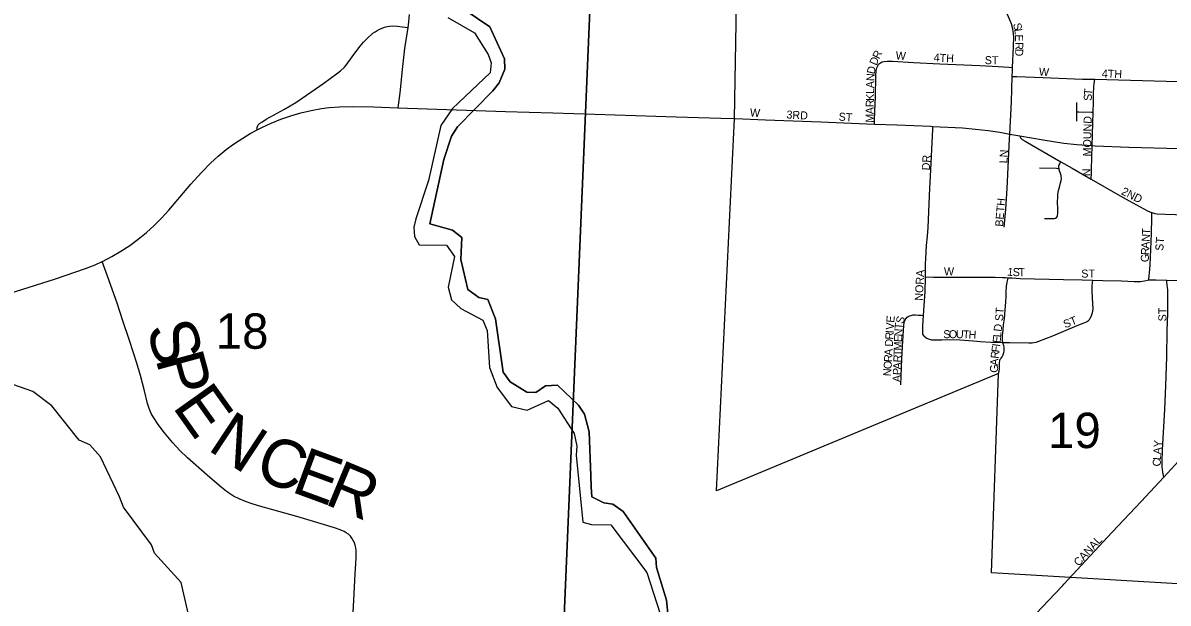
# Model space of a CAD drawing. Extents: x 0 to 34, y 0 to 22.
# Drawn here: x 3.441 to 4.796, y 17.694 to 18.381 of the extents above; entities that cross this region are included whole.
import ezdxf

# ---------------------------------------------------------------- set-up
doc = ezdxf.new("R2010")
doc.units = 0
for name, color, linetype in [('GM_X_City_Street', 7, 'Continuous'), ('GM_X_City_Street_Text', 7, 'Continuous'), ('GM_X_Corporation', 7, 'Continuous'), ('GM_X_County_Road', 7, 'Continuous'), ('GM_X_Minor_River', 7, 'Continuous'), ('GM_X_Section', 7, 'Continuous'), ('GM_X_Section_Text', 7, 'Continuous'), ('GM_X_Township_Road', 7, 'Continuous'), ('GM_X_Township_Road_Text', 7, 'Continuous')]:
    doc.layers.add(name, color=color, linetype=linetype)

msp = doc.modelspace()

# ---------------------------------------------------------------- linework, layer by layer
at = {"layer": 'GM_X_City_Street'}
for points in [[(4.6123, 18.3277), (4.6134, 18.3522), (4.6135, 18.3645), (4.6129, 18.3706), (4.6124, 18.3736), (4.6108, 18.3794), (4.6075, 18.388), (4.5998, 18.4049), (4.5947, 18.4162), (4.5925, 18.422), (4.5907, 18.4281), (4.5897, 18.4343), (4.5893, 18.4405), (4.5894, 18.453), (4.5903, 18.4799), (4.5904, 18.4842)], [(4.4486, 18.261), (4.4488, 18.2646), (4.4493, 18.2765), (4.45, 18.293), (4.4504, 18.3183), (4.4508, 18.3242), (4.4515, 18.3274), (4.4526, 18.3299), (4.4537, 18.3317)], [(4.4537, 18.3317), (4.4547, 18.3327), (4.4559, 18.3335), (4.458, 18.3344), (4.4602, 18.3351), (4.4638, 18.3355), (4.4701, 18.3354), (4.4951, 18.3338), (4.5263, 18.3321), (4.5733, 18.3302), (4.5951, 18.3291), (4.6076, 18.3281), (4.6123, 18.3277)], [(4.6119, 18.3173), (4.6121, 18.3244), (4.6123, 18.3277)], [(4.6089, 18.2491), (4.6109, 18.2872), (4.6119, 18.3173)], [(4.6119, 18.3173), (4.6172, 18.3171), (4.6482, 18.316), (4.6948, 18.3142), (4.7094, 18.3139)], [(4.7076, 18.2752), (4.7078, 18.2868), (4.708, 18.2961), (4.7085, 18.3054), (4.7088, 18.3084), (4.7094, 18.3139)], [(4.7094, 18.3139), (4.7939, 18.3118), (4.8368, 18.3107), (4.8711, 18.3097)], [(4.6883, 18.2754), (4.6884, 18.2865)], [(4.6882, 18.2645), (4.6883, 18.2754)], [(4.6883, 18.2754), (4.6908, 18.2754), (4.7054, 18.2752), (4.7076, 18.2752)], [(4.7065, 18.2354), (4.7073, 18.2619), (4.7076, 18.2752)], [(4.2837, 18.2675), (4.2838, 18.2675), (4.3199, 18.266), (4.3852, 18.2635), (4.4486, 18.261)], [(4.4486, 18.261), (4.4752, 18.2599), (4.5156, 18.2583), (4.5178, 18.2582)], [(4.5091, 18.0802), (4.5091, 18.0955), (4.5094, 18.1018), (4.5104, 18.1174), (4.5114, 18.1284), (4.5122, 18.1387), (4.5139, 18.1759), (4.5143, 18.1851), (4.5151, 18.199), (4.5177, 18.2551), (4.5178, 18.2582)], [(4.5178, 18.2582), (4.5528, 18.2564), (4.5684, 18.2551), (4.5835, 18.2535), (4.5973, 18.2512), (4.6089, 18.2491)], [(4.6022, 18.1388), (4.6041, 18.1602), (4.6056, 18.1848), (4.6086, 18.2433), (4.6089, 18.2491)], [(4.6089, 18.2491), (4.6207, 18.247)], [(4.6207, 18.247), (4.6217, 18.2447), (4.6236, 18.2428), (4.6269, 18.2407), (4.6694, 18.2163)], [(4.6207, 18.247), (4.6482, 18.2422), (4.6727, 18.2385), (4.6882, 18.2368), (4.7065, 18.2354)], [(4.7053, 18.1957), (4.7056, 18.2032), (4.7057, 18.2072), (4.7065, 18.2354)], [(4.7065, 18.2354), (4.7098, 18.2351), (4.7498, 18.2337), (4.8247, 18.2318), (4.8651, 18.2306), (4.8682, 18.2305)], [(4.6672, 18.2084), (4.667, 18.2099), (4.6671, 18.2114), (4.6675, 18.2127), (4.6682, 18.214), (4.6694, 18.2163)], [(4.6694, 18.2163), (4.6828, 18.2086), (4.7053, 18.1957)], [(4.6441, 18.2092), (4.6641, 18.2086), (4.6672, 18.2084)], [(4.6501, 18.1493), (4.6586, 18.1491), (4.6615, 18.1491), (4.6631, 18.1496), (4.6644, 18.1508), (4.6653, 18.1527), (4.6657, 18.1553), (4.6656, 18.16), (4.6655, 18.1694), (4.6656, 18.1742), (4.6659, 18.1779), (4.6666, 18.1824), (4.6682, 18.1878), (4.6691, 18.1913), (4.6697, 18.194), (4.6699, 18.1963), (4.6696, 18.2), (4.6691, 18.2026), (4.6675, 18.2069), (4.6672, 18.2084)], [(4.7053, 18.1957), (4.7366, 18.1778), (4.7501, 18.1701), (4.7719, 18.1584), (4.7747, 18.1572), (4.7769, 18.1564)], [(4.7736, 18.0765), (4.7739, 18.0818), (4.7741, 18.0849), (4.7749, 18.0942), (4.7755, 18.1034), (4.7759, 18.1127), (4.7766, 18.1313), (4.7768, 18.15), (4.7769, 18.1564)], [(4.7769, 18.1564), (4.7804, 18.1553), (4.7834, 18.1548), (4.7926, 18.1542), (4.8652, 18.152)], [(4.5069, 18.0346), (4.5077, 18.0462), (4.5086, 18.0626), (4.5091, 18.0802)], [(4.5091, 18.0802), (4.5186, 18.08), (4.5306, 18.0798), (4.5585, 18.0797), (4.5914, 18.0798), (4.6004, 18.0796), (4.604, 18.0794), (4.607, 18.0792)], [(4.6008, 18.0026), (4.6004, 18.0044), (4.6001, 18.0066), (4.6001, 18.01), (4.6005, 18.014), (4.601, 18.0176), (4.6016, 18.0235), (4.6025, 18.0305), (4.6036, 18.041), (4.6043, 18.0502), (4.6045, 18.0574), (4.6045, 18.0624), (4.6051, 18.0687), (4.6057, 18.074), (4.6065, 18.0771), (4.607, 18.0792)], [(4.607, 18.0792), (4.6114, 18.0789), (4.6213, 18.0784), (4.6726, 18.0772), (4.6944, 18.0768), (4.707, 18.0763)], [(4.7042, 18.0313), (4.7055, 18.0339), (4.7064, 18.0367), (4.7071, 18.0397), (4.7074, 18.0422), (4.7073, 18.0482), (4.7063, 18.0634), (4.7063, 18.0667), (4.7065, 18.0692), (4.7068, 18.074), (4.707, 18.0763)], [(4.707, 18.0763), (4.7189, 18.0759), (4.7409, 18.0753), (4.7562, 18.0748), (4.7635, 18.0748), (4.7683, 18.0754), (4.772, 18.0764), (4.7736, 18.0765)], [(4.7736, 18.0765), (4.7768, 18.0767), (4.7819, 18.0767), (4.7946, 18.0763)], [(4.791, 17.843), (4.7902, 17.8491), (4.7894, 17.8553), (4.7892, 17.8615), (4.7898, 17.8754), (4.7923, 17.9234), (4.7935, 17.9513), (4.7947, 17.9854), (4.7952, 18.0164), (4.7959, 18.0371), (4.796, 18.0552), (4.7959, 18.0649), (4.7949, 18.0734), (4.7946, 18.0763)], [(4.7946, 18.0763), (4.8624, 18.0744)], [(4.48, 17.9524), (4.4813, 17.983), (4.4823, 18.0043), (4.4834, 18.0227), (4.4838, 18.0257), (4.4842, 18.0274), (4.485, 18.0293), (4.4858, 18.0305), (4.4874, 18.0323), (4.4887, 18.0332), (4.4902, 18.0339), (4.4921, 18.0346), (4.4944, 18.0351), (4.4975, 18.0352), (4.5006, 18.035), (4.504, 18.0348), (4.5069, 18.0346)], [(4.5076, 18.0099), (4.5067, 18.0111), (4.5061, 18.0123), (4.5058, 18.0141), (4.5059, 18.0181), (4.506, 18.0222), (4.5069, 18.0346)], [(4.6008, 18.0026), (4.6084, 18.0025), (4.6314, 18.0022), (4.6353, 18.0023), (4.6375, 18.0025), (4.6402, 18.0031), (4.6431, 18.0039), (4.6597, 18.0105), (4.6887, 18.0225), (4.6958, 18.0254), (4.6995, 18.027), (4.701, 18.0278), (4.7022, 18.0286), (4.7032, 18.0297), (4.7042, 18.0313)], [(4.5076, 18.0099), (4.5094, 18.0084), (4.5106, 18.0077), (4.5122, 18.007), (4.5139, 18.0064), (4.5163, 18.0058), (4.5182, 18.0058), (4.5214, 18.0057), (4.5284, 18.0058), (4.5373, 18.006), (4.5499, 18.0056), (4.5661, 18.0044), (4.5738, 18.0038), (4.5868, 18.0029), (4.6008, 18.0026)], [(4.5956, 17.9659), (4.5965, 17.9687), (4.5967, 17.9717), (4.5966, 17.9755), (4.5967, 17.9783), (4.5971, 17.9809), (4.5977, 17.9826), (4.5986, 17.984), (4.5997, 17.9855), (4.6009, 17.9878), (4.6018, 17.9906), (4.6022, 17.9924), (4.6023, 17.9952), (4.6022, 17.9972), (4.6018, 17.999), (4.6012, 18.0007), (4.6008, 18.0026)], [(4.791, 17.843), (4.8172, 17.8715), (4.8363, 17.892), (4.8447, 17.9013), (4.8506, 17.9084), (4.8544, 17.9137), (4.8566, 17.9182)], [(4.6715, 17.7152), (4.6729, 17.7167), (4.7301, 17.778), (4.7644, 17.8142), (4.791, 17.843)]]:
    msp.add_lwpolyline(points, dxfattribs=at)
at = {"layer": 'GM_X_Corporation'}
msp.add_lwpolyline([(4.9748, 17.7073), (4.5871, 17.7299), (4.5956, 17.9659), (4.2619, 17.827), (4.283, 18.2672), (4.2872, 18.4939), (4.5904, 18.485), (4.6993, 18.4813), (4.7077, 18.686), (4.5833, 18.6907), (4.4929, 18.7467), (4.5036, 18.7609), (4.4834, 18.7705), (4.4977, 18.7812), (4.5483, 18.7776), (4.7237, 18.8109), (5.1009, 18.7931)], dxfattribs=at)
at = {"layer": 'GM_X_County_Road'}
for points in [[(3.8982, 18.3905), (3.8969, 18.3781), (3.8964, 18.3752)], [(3.8964, 18.3752), (3.8927, 18.3505), (3.8902, 18.3289), (3.887, 18.298), (3.8847, 18.2802)], [(3.7184, 18.2541), (3.7237, 18.2569), (3.7349, 18.2622), (3.7464, 18.2668), (3.7581, 18.2708), (3.77, 18.2742), (3.7821, 18.277), (3.7942, 18.2792), (3.8034, 18.2804), (3.8158, 18.2813), (3.8313, 18.2817), (3.8561, 18.2813), (3.8847, 18.2802)], [(3.8847, 18.2802), (4.0123, 18.276), (4.0682, 18.2742), (4.1179, 18.2727), (4.2142, 18.2696), (4.2669, 18.2679), (4.2837, 18.2675)], [(3.5349, 18.0983), (3.5351, 18.0984), (3.5462, 18.1042), (3.557, 18.1105), (3.5674, 18.1174), (3.5774, 18.1247), (3.5871, 18.1326), (3.5964, 18.141), (3.6052, 18.1498), (3.6137, 18.1589), (3.6398, 18.1897), (3.6522, 18.2036), (3.663, 18.2147), (3.6721, 18.2231), (3.6816, 18.231), (3.6891, 18.2365), (3.6968, 18.2416), (3.7101, 18.2496), (3.7184, 18.2541)], [(3.1436, 17.9953), (3.1996, 17.9978), (3.2183, 17.999), (3.2306, 18.0004), (3.243, 18.0023), (3.2522, 18.0041), (3.2612, 18.0065), (3.273, 18.0102), (3.2908, 18.0158), (3.3439, 18.0333), (3.3763, 18.044), (3.4324, 18.0627), (3.4797, 18.0779), (3.5149, 18.0901), (3.5266, 18.0945), (3.5349, 18.0983)], [(4.2855, 17.341), (4.2918, 17.3468), (4.325, 17.3794), (4.3475, 17.4009), (4.4085, 17.4585), (4.4377, 17.4863), (4.4812, 17.528), (4.5413, 17.5847), (4.5865, 17.6273), (4.6065, 17.6468), (4.626, 17.6668), (4.6622, 17.7052), (4.6715, 17.7152)]]:
    msp.add_lwpolyline(points, dxfattribs=at)
at = {"layer": 'GM_X_Minor_River'}
for points in [[(4.2049, 17.6739), (4.2025, 17.6978), (4.1907, 17.7365), (4.1899, 17.7475), (4.1514, 17.8024), (4.1393, 17.8111), (4.1283, 17.8129), (4.1142, 17.8201), (4.1134, 17.8318), (4.113, 17.8447), (4.1113, 17.8967), (4.1056, 17.9179), (4.0987, 17.9285), (4.0736, 17.952), (4.0596, 17.9512), (4.0479, 17.9435), (4.0373, 17.9439), (4.0175, 17.956), (4.0092, 17.9673), (4.0002, 18.0306), (3.9911, 18.0534), (3.9804, 18.0556), (3.9675, 18.0654), (3.9591, 18.1007), (3.9605, 18.1269), (3.9495, 18.1355), (3.9226, 18.143), (3.939, 18.219), (3.9484, 18.2467), (3.9552, 18.2577), (3.9971, 18.3003), (4.0046, 18.3098), (4.0114, 18.3258), (4.011, 18.3383), (3.9934, 18.3758), (3.9216, 18.4249)], [(3.9216, 18.4249), (3.9934, 18.3758), (4.011, 18.3383), (4.0114, 18.3258), (4.0046, 18.3098), (3.9971, 18.3003), (3.9552, 18.2577), (3.9484, 18.2467), (3.939, 18.219), (3.9226, 18.143), (3.9495, 18.1355), (3.9605, 18.1269), (3.9591, 18.1007), (3.9675, 18.0654), (3.9804, 18.0556), (3.9911, 18.0534), (4.0002, 18.0306), (4.0092, 17.9673), (4.0175, 17.956), (4.0373, 17.9439), (4.0479, 17.9435), (4.0596, 17.9512), (4.0736, 17.952), (4.0987, 17.9285), (4.1056, 17.9179), (4.1113, 17.8967), (4.113, 17.8447), (4.1134, 17.8318), (4.1142, 17.8201), (4.1283, 17.8129), (4.1393, 17.8111), (4.1514, 17.8024), (4.1899, 17.7475), (4.1907, 17.7365), (4.2025, 17.6978), (4.2049, 17.6739)], [(3.9437, 18.387), (3.9756, 18.3689), (3.9916, 18.3432), (3.9951, 18.3333), (3.994, 18.3215), (3.9494, 18.2793), (3.9354, 18.2592), (3.9209, 18.1943), (3.9059, 18.1487), (3.9036, 18.1388), (3.9044, 18.1278), (3.9101, 18.118), (3.9423, 18.1177), (3.9519, 18.1041), (3.9444, 18.068), (3.9482, 18.0529), (3.9593, 18.0426), (3.9851, 18.0291), (3.9904, 18.0169), (3.9932, 17.973), (4.0024, 17.9491), (4.0191, 17.9268), (4.0377, 17.9226), (4.0631, 17.9337), (4.0741, 17.9247), (4.0935, 17.8947), (4.0966, 17.88), (4.0959, 17.8693), (4.1037, 17.7901), (4.1139, 17.7871), (4.1367, 17.7868), (4.1793, 17.7304), (4.1992, 17.6694)], [(3.6381, 17.6644), (3.6391, 17.6722), (3.6284, 17.7184), (3.5968, 17.7532), (3.593, 17.7631), (3.5602, 17.8078), (3.5553, 17.8199), (3.5328, 17.8672), (3.5202, 17.8816), (3.5077, 17.8869), (3.4753, 17.9277), (3.4526, 17.9447), (3.3812, 17.9695)]]:
    msp.add_lwpolyline(points, dxfattribs=at)
at = {"layer": 'GM_X_Section'}
for points in [[(4.1166, 18.5074), (4.0746, 17.5111), (3.0654, 17.5504), (3.0927, 18.5447)], [(4.1166, 18.5074), (5.1195, 18.4619), (5.0805, 17.4591), (4.0746, 17.5111)]]:
    msp.add_lwpolyline(points, close=True, dxfattribs=at)
at = {"layer": 'GM_X_Township_Road'}
for points in [[(3.7184, 18.2541), (3.7184, 18.2567), (3.7188, 18.2582), (3.7196, 18.2602), (3.7211, 18.2615), (3.7236, 18.2633), (3.7288, 18.2667), (3.7505, 18.2786), (3.7638, 18.2866), (3.7767, 18.2951), (3.797, 18.3094), (3.8121, 18.3202), (3.817, 18.324), (3.8215, 18.3283), (3.8235, 18.3306), (3.8325, 18.3432), (3.84, 18.353), (3.844, 18.3578), (3.8483, 18.3622), (3.8553, 18.3684), (3.8578, 18.3702), (3.8604, 18.3718), (3.8631, 18.3733), (3.866, 18.3746), (3.8689, 18.3756), (3.8719, 18.3764), (3.875, 18.3768), (3.878, 18.377), (3.8842, 18.3768), (3.8904, 18.376), (3.8964, 18.3752)], [(3.8316, 17.676), (3.8326, 17.6977), (3.8343, 17.7287), (3.8353, 17.7473), (3.8354, 17.7566), (3.8351, 17.7597), (3.8344, 17.7627), (3.8334, 17.7656), (3.832, 17.7684), (3.8304, 17.7711), (3.8285, 17.7735), (3.8262, 17.7756), (3.8237, 17.7774), (3.821, 17.779), (3.8163, 17.781), (3.8099, 17.7833), (3.7926, 17.7883), (3.765, 17.7965), (3.7366, 17.8045), (3.7197, 17.8094), (3.7113, 17.8122), (3.7045, 17.8145), (3.6969, 17.8177), (3.6904, 17.8207), (3.6844, 17.8246), (3.6798, 17.8279), (3.6732, 17.8334), (3.6591, 17.8455), (3.6358, 17.866), (3.6269, 17.8747), (3.6185, 17.8838), (3.6085, 17.8956), (3.6009, 17.9054), (3.5958, 17.9132), (3.5928, 17.9187), (3.5904, 17.9244), (3.5885, 17.9303), (3.585, 17.9454), (3.5802, 17.9633), (3.5757, 17.9782), (3.5671, 18.0047), (3.5593, 18.0283), (3.5524, 18.0489), (3.5413, 18.0811), (3.5349, 18.0983)]]:
    msp.add_lwpolyline(points, dxfattribs=at)

# ---------------------------------------------------------------- texts
at = {"layer": 'GM_X_City_Street_Text'}
for s, rotation, p in [('S', 283.2014, (4.6127, 18.3794)), ('L', 277.508, (4.6141, 18.3732)), ('E', 272.0493, (4.615, 18.3668)), ('R', 270.1215, (4.6153, 18.3577)), ('D', 66.6034, (4.451, 18.3296)), ('R', 63.6522, (4.4543, 18.3371)), ('W', 355.6039, (4.4736, 18.3376)), ('4TH', 356.7313, (4.5186, 18.3351)), ('ST', 0, (4.5793, 18.3318)), ('D', 270, (4.6153, 18.3502)), ('D', 78.2486, (4.4488, 18.3195)), ('W', 355.8437, (4.6431, 18.3184)), ('4TH', 358.3643, (4.7177, 18.316)), ('A', 88.929, (4.4483, 18.3033)), ('N', 87.3329, (4.4485, 18.3116)), ('K', 88.929, (4.4481, 18.2883)), ('L', 88.9395, (4.4482, 18.2966)), ('S', 88.9072, (4.7059, 18.2883)), ('T', 84.8575, (4.706, 18.2948)), ('R', 88.9314, (4.4479, 18.2808)), ('W', 355.5872, (4.3011, 18.2701)), ('3RD', 356.8219, (4.3444, 18.2676)), ('ST', 356.4262, (4.4061, 18.2651)), ('M', 88.9253, (4.4476, 18.2625)), ('A', 88.9343, (4.4478, 18.2725)), ('MOUND', 89.0596, (4.705, 18.2226)), ('LN', 86.989, (4.6059, 18.2143)), ('DR', 86.989, (4.5142, 18.206)), ('N', 90, (4.7042, 18.1992)), ('2ND', 333.4313, (4.7401, 18.1783)), ('BETH', 85.3634, (4.6009, 18.1393)), ('T', 87.2005, (4.7747, 18.1299)), ('A', 87.2227, (4.7739, 18.1132)), ('N', 87.2009, (4.7743, 18.1216)), ('ST', 86.4262, (4.7905, 18.1108)), ('G', 88.929, (4.7734, 18.0975)), ('R', 87.4978, (4.7735, 18.1057)), ('NORA', 87.066, (4.5059, 18.0518)), ('W', 0, (4.531, 18.0818)), ('1', 353.7736, (4.6055, 18.0818)), ('S', 359.1662, (4.6123, 18.0811)), ('T', 359.8574, (4.6191, 18.081)), ('ST', 0, (4.6935, 18.0793)), ('ST', 86.4254, (4.6009, 18.0276)), ('ST', 90, (4.7942, 18.0275)), ('V', 86.6264, (4.4716, 18.0174)), ('E', 84.8575, (4.4721, 18.0256)), ('T', 83.7322, (4.4818, 18.0177)), ('S', 71.4527, (4.4825, 18.0238)), ('ST', 21.8039, (4.6745, 18.0192)), ('R', 86.6221, (4.4709, 18.0057)), ('I', 86.5873, (4.4714, 18.0132)), ('N', 87.7697, (4.4815, 18.0096)), ('S', 359.9727, (4.5302, 18.0076)), ('O', 359.9563, (4.5368, 18.0076)), ('U', 359.0164, (4.5451, 18.0076)), ('T', 357.622, (4.5534, 18.0075)), ('H', 357.5076, (4.56, 18.0072)), ('L', 85.671, (4.5986, 18.0084)), ('D', 83.6477, (4.5991, 18.015)), ('D', 86.6264, (4.4704, 17.9974)), ('M', 88.0144, (4.481, 17.9929)), ('E', 88.0327, (4.4813, 18.0029)), ('F', 82.1905, (4.5964, 17.9904)), ('I', 82.2264, (4.5973, 17.9971)), ('E', 84.1977, (4.5979, 18.0015)), ('R', 86.629, (4.4694, 17.9791)), ('A', 86.6104, (4.4698, 17.9866)), ('R', 88.0083, (4.4805, 17.9788)), ('T', 88.0327, (4.4807, 17.9863)), ('R', 82.5979, (4.5954, 17.983)), ('N', 86.6104, (4.4684, 17.9624)), ('O', 86.6104, (4.4689, 17.9708)), ('P', 88.0053, (4.4799, 17.9638)), ('A', 88.0337, (4.4802, 17.9705)), ('G', 89.847, (4.595, 17.9667)), ('A', 87.3766, (4.5951, 17.9749)), ('A', 88.0326, (4.4797, 17.9555)), ('A', 86.4346, (4.7881, 17.8699)), ('Y', 86.4348, (4.7886, 17.8782)), ('C', 88.8586, (4.7875, 17.8558)), ('L', 86.8565, (4.7877, 17.8632)), ('CANAL', 47.5657, (4.6905, 17.7371))]:
    msp.add_text(s, height=0.00947, rotation=rotation, dxfattribs=at).set_placement(p)
at = {"layer": 'GM_X_Section_Text'}
for s, p in [('18', (3.6693, 17.9951)), ('19', (4.6543, 17.8776))]:
    msp.add_text(s, height=0.04186, rotation=0, dxfattribs=at).set_placement(p)
at = {"layer": 'GM_X_Township_Road_Text'}
for s, rotation, p in [('S', 287.3109, (3.5865, 18.0194)), ('P', 285.2418, (3.5977, 17.9833)), ('E', 305.473, (3.6171, 17.9266)), ('N', 326.5949, (3.6582, 17.8762)), ('C', 340.4525, (3.7133, 17.842)), ('E', 339.784, (3.7571, 17.8264)), ('R', 337.3687, (3.7964, 17.812))]:
    msp.add_text(s, height=0.0568, rotation=rotation, dxfattribs=at).set_placement(p)

doc.saveas('drawing.dxf')
